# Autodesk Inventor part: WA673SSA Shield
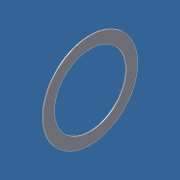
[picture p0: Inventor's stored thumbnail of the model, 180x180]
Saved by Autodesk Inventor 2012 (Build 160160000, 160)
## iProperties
Category: PARTsolutions
Created: 2011-07
Part Number: WA673SSA Shield
Catalog Web Link: www.cadenas.de
Description: Six types s - Metric system sizes
Document SubType Name: Modeling
Designer: PARTsolutions
Density: 1 g/cm^3
Material: Par défaut
NB: WA673SSA Shield
NN: Six types s
NT: Metric system sizes
NBSYN: $ORDER. Shield
LINA: WA673SSA Shield
SD: 3.0
D: 6
B: 2.0
R: 0.08
ORDER: WA673SSA
CR: 242
COR: 94
CRF: 25
CORF: 9,5
LSG: 60 000
LSO: 71 000
MASS: 0.20
ORDER1: 673
D1: 7.2
D2: 7.2
C1: 0.6
C2: 0.6
WSS: WA673SSA
WDS: SSA
UTWF: FL673
FORSS: FLWA673SA
FORDS: SSA
DA1: 3,6
DA2: 4,1
DA: 5,4
RAS: 0,08
MASS1: 0.26
B1: 2.5
VERS: 3
X: 1.500
N: 9
O: 14.130
RB: 0.444
KT: DUMMY
SUPPLIER: NTN
ARTICLENO: WA673SSA Shield
BOMINFO: WA673SSA Shield
CREATOR: CADENAS GmbH
PSOL_IDENT_0: {\\10.0.0.251\ps_data\23d-libs\ntn\ball_roller_bearings\miniature_extra_small_bb\metric_system_sizes
PSOL_IDENT_1: \mss_s.prj},180 {VTYP=3D},{NB=WA673SSA Shield},{LINA=WA673SSA Shield},{NN=Six types s},{DATE=11.12.2
PSOL_IDENT_2: 007 08:48:24},{GEOMDATE=02.04.2007 12:30:00},{VERSION=},{LINEID=12590},{LINESUBID=-1},{WBVAR=}  {NB=
PSOL_IDENT_3: WA673SSA Shield},{LINA=WA673SSA Shield},{KT=DUMMY},{IDNR=},{SD=3.0},{D=6},{B=2.0},{R=0.08},{ORDER=WA
PSOL_IDENT_4: 673SSA},{CR=242},{COR=94},{CRF=25},{CORF=9,5},{LSG=60 000},{LSO=71 000},{MASS=0.20},{ORDER1=673},{D1
PSOL_IDENT_5: =7.2},{D2=7.2},{C1=0.6},{C2=0.6},{WSS=WA673SSA},{WDS=SSA},{UTWF=FL673},{FORSS=FLWA673SA},{FORDS=SSA}
PSOL_IDENT_6: ,{DA1=3,6},{DA2=4,1},{DA=5,4},{RAS=0,08},{MASS1=0.26},{B1=2.5},{VERS=3},{X=1.5},{N=9},{O=14.13},{RB=
PSOL_IDENT_7: 0.444}
Title: WA673SSA Shield
Author: Cadenas PARTsolutions
Comments: Metric system sizes
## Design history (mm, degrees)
sketch "Sketch_1"
  geometry: L1 (-0.014, 0)-(-0.056, 0); L2 (-0.056, 1.98)-(-0.014, 1.98); L3 (-0.014, 1.98)-(-0.014, 2.616); L4 (-0.014, 2.616)-(-0.056, 2.616); L5 (-0.056, 2.616)-(-0.056, 1.98)
  constraints: 10 end point
revolve "Revolution1" sketch "Sketch_1" stored, may be unused: angle "d0" = 360 deg
node "mss_s_XY"
node "mss_s_YZ"
node "mss_s_ZX"
node "mss_s_X"
node "mss_s_Y"
node "mss_s_Z"
node "mss_s_Center"
node "Solide1"
node "Corps solides"
node "Corps surfaciques"
